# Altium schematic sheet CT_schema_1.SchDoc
size 395 x 454 mm
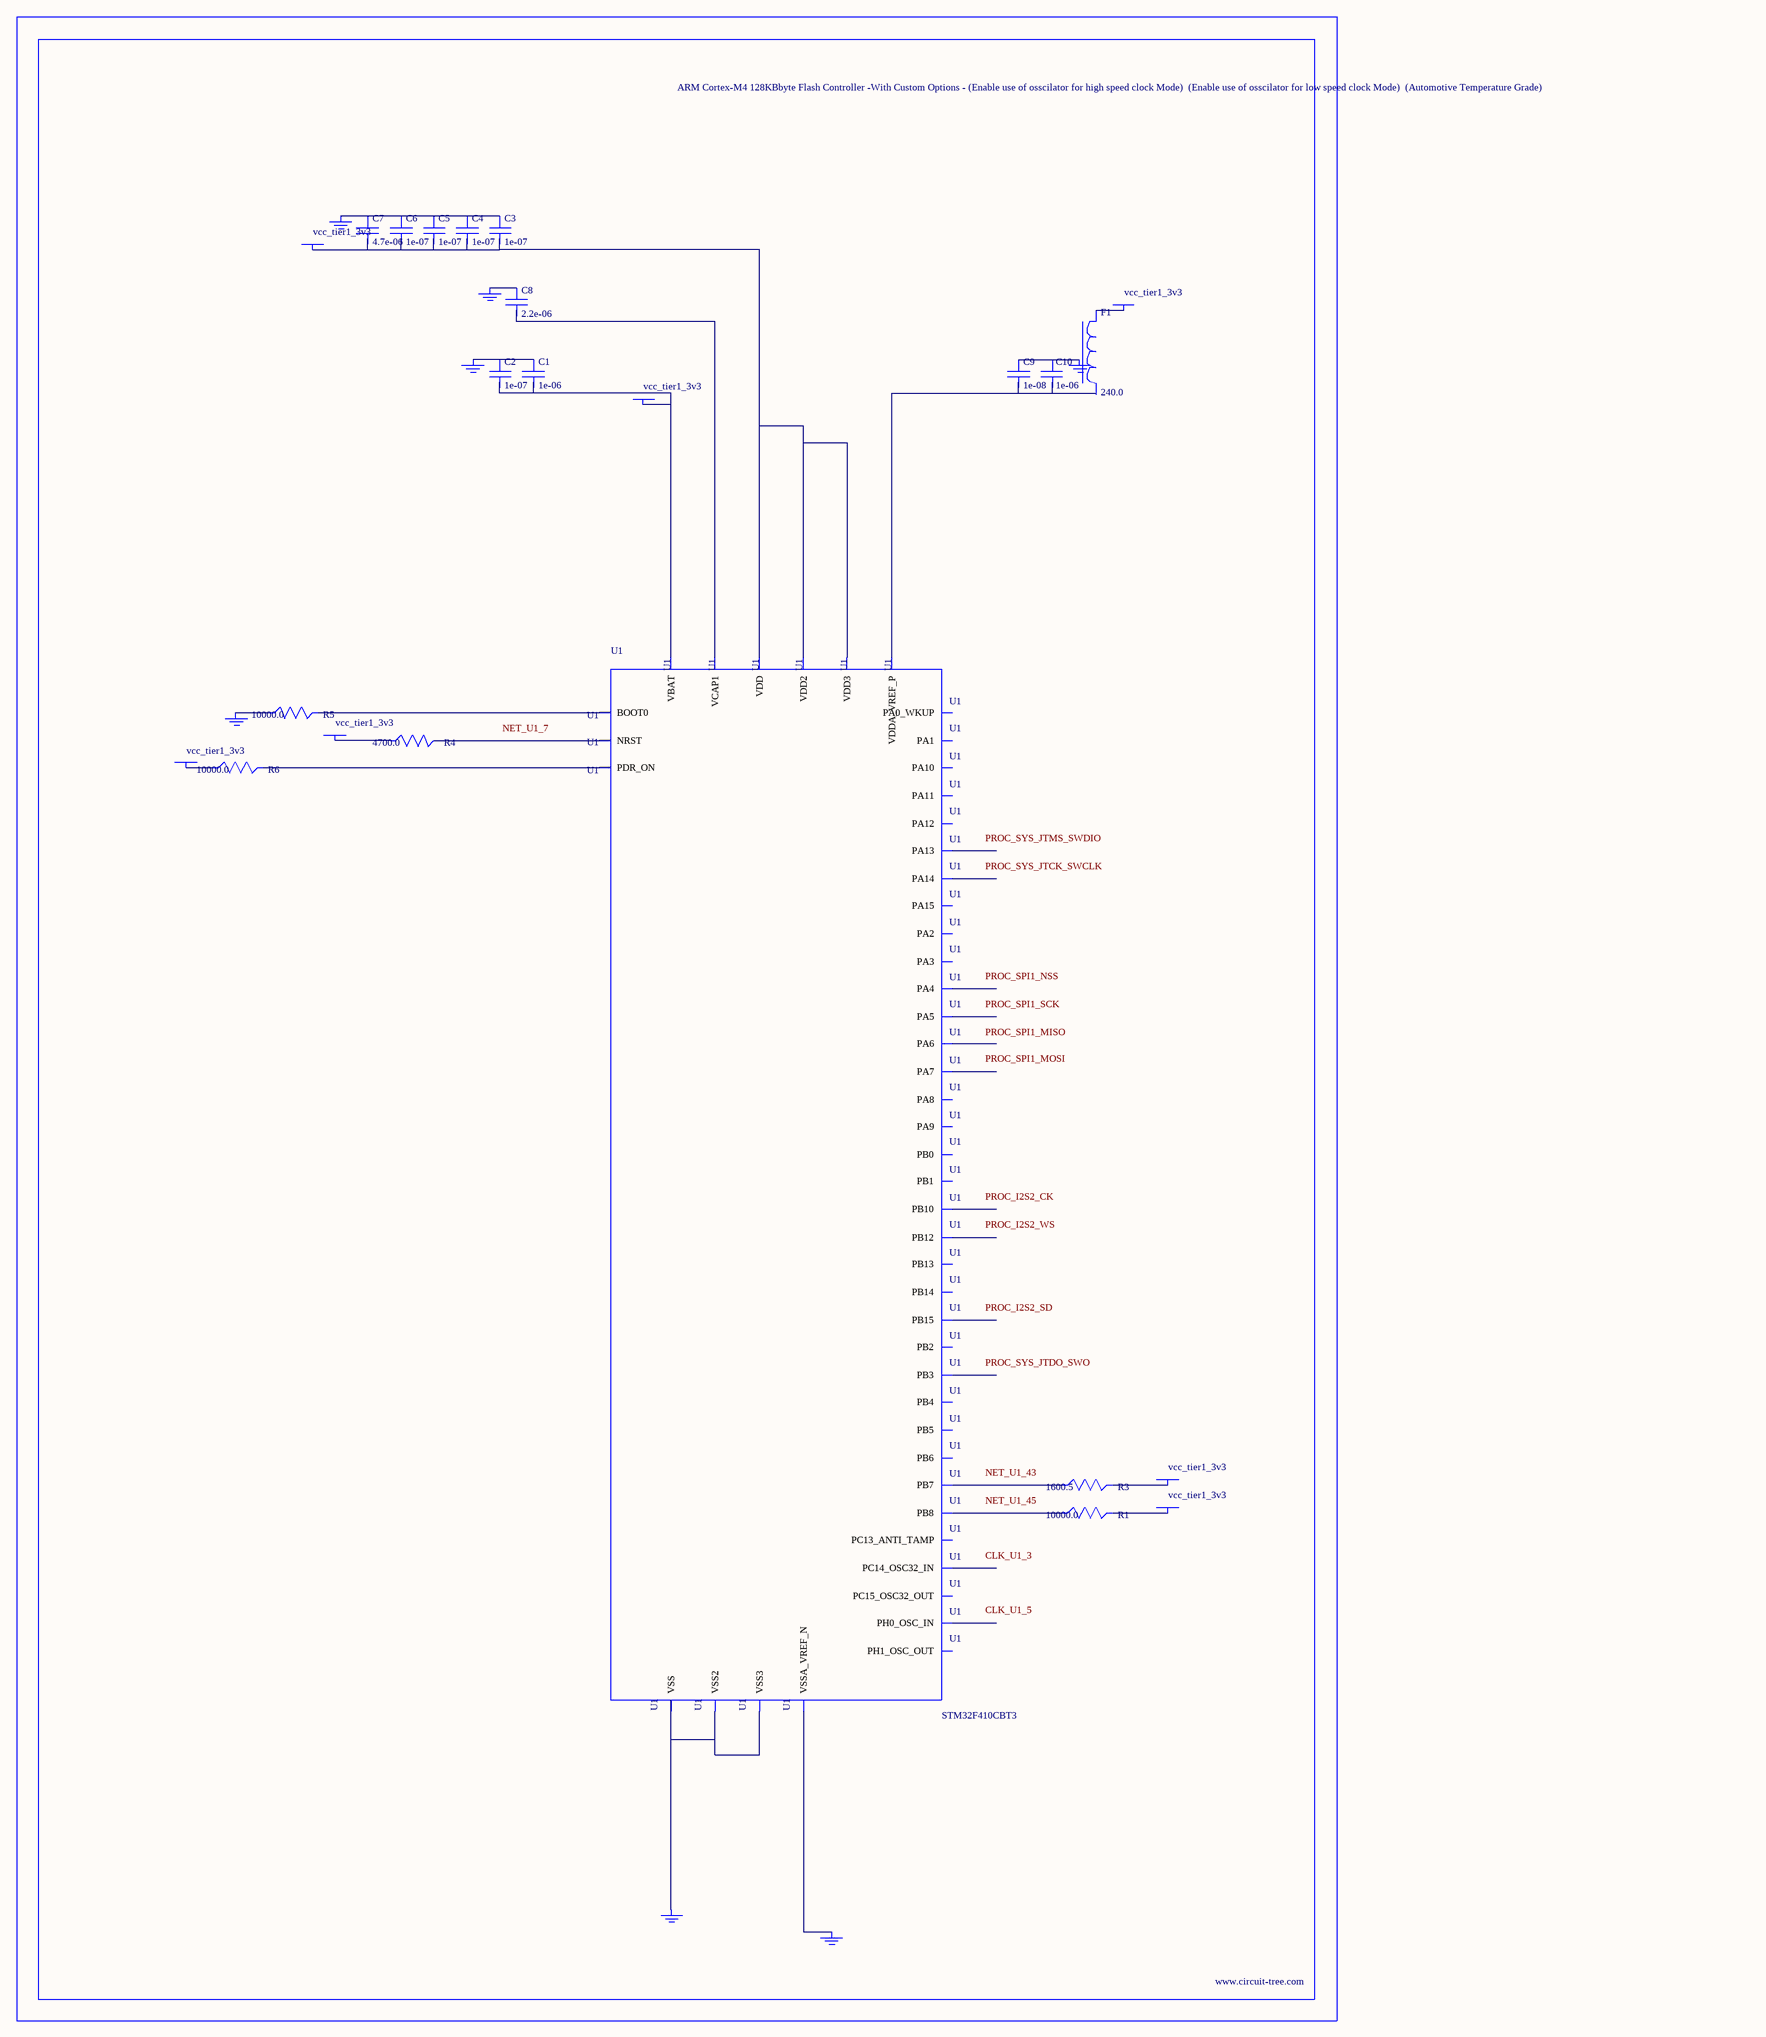
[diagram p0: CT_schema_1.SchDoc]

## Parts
BORDER0  (no value)
C1  1e-06  [C0603]
C2  1e-07  [C0603]
C3  1e-07  [C0603]
C4  1e-07  [C0603]
C5  1e-07  [C0603]
C6  1e-07  [C0603]
C7  4.7e-06  [C0603]
C8  2.2e-06  [C0603]
C9  1e-08  [C0603]
C10  1e-06  [C0603]
F1  240.0  [L0603]
GND_INSTANCE_0_0  (no value)
GND_INSTANCE_0_1  (no value)
GND_INSTANCE_0_2  (no value)
GND_INSTANCE_0_3  (no value)
GND_INSTANCE_0_4  (no value)
GND_INSTANCE_0_5  (no value)
GND_INSTANCE_0_6  (no value)
POWER_INSTANCE_0_0  vcc_tier1_3v3
POWER_INSTANCE_0_1  vcc_tier1_3v3
POWER_INSTANCE_0_2  vcc_tier1_3v3
POWER_INSTANCE_0_3  vcc_tier1_3v3
POWER_INSTANCE_0_4  vcc_tier1_3v3
POWER_INSTANCE_0_5  vcc_tier1_3v3
POWER_INSTANCE_0_6  vcc_tier1_3v3
R1  10000.0  [R0603]
R3  1600.5  [R0603]
R4  4700.0  [R0603]
R5  10000.0  [R0603]
R6  10000.0  [R0603]
U1  STM32F410CBT3  [LQFP48]

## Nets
NetC1_1: C1.1 C2.1 GND_INSTANCE_0_0.0(GND)
NetC1_2: C1.2 C2.2 POWER_INSTANCE_0_0.0(PWR) U1.1(VBAT)
NetC3_1: C3.1 C4.1 C5.1 C6.1 C7.1 GND_INSTANCE_0_4.0(GND)
NetC3_2: C3.2 C4.2 C5.2 C6.2 C7.2 POWER_INSTANCE_0_2.0(PWR) U1.24(VDD) U1.36(VDD2) U1.48(VDD3)
NetC8_1: C8.1 GND_INSTANCE_0_3.0(GND)
NetC8_2: C8.2 U1.22(VCAP1)
NetC9_1: C9.1 C10.1 GND_INSTANCE_0_2.0(GND)
NetC9_2: C9.2 C10.2 U1.9(VDDA_VREF_P)
NetF1_1: F1.1 POWER_INSTANCE_0_1.0(PWR)
NetGND_INSTANCE_0_1_0: GND_INSTANCE_0_1.0(GND) U1.8(VSSA_VREF_N)
NetGND_INSTANCE_0_5_0: GND_INSTANCE_0_5.0(GND) R5.1
NetGND_INSTANCE_0_6_0: GND_INSTANCE_0_6.0(GND) U1.23(VSS) U1.35(VSS2) U1.46(VSS3)
NetPOWER_INSTANCE_0_3_0: POWER_INSTANCE_0_3.0(PWR) R6.1
NetPOWER_INSTANCE_0_4_0: POWER_INSTANCE_0_4.0(PWR) R4.1
NetPOWER_INSTANCE_0_5_0: POWER_INSTANCE_0_5.0(PWR) R3.2
NetPOWER_INSTANCE_0_6_0: POWER_INSTANCE_0_6.0(PWR) R1.2
NetR1_1: R1.1 U1.45(PB8)
NetR3_1: R3.1 U1.43(PB7)
NetR4_2: R4.2 U1.7(NRST)
NetR5_2: R5.2 U1.44(BOOT0)
NetR6_2: R6.2 U1.47(PDR_ON)

Not connected (* = marked no-connect by the designer): F1 2; U1 2(PC13_ANTI_TAMP) 3(PC14_OSC32_IN) 4(PC15_OSC32_OUT) 5(PH0_OSC_IN) 6(PH1_OSC_OUT) 10(PA0_WKUP) 11(PA1) 12(PA2) 13(PA3) 14(PA4) 15(PA5) 16(PA6) 17(PA7) 18(PB0) 19(PB1) 20(PB2) 21(PB10) 25(PB12) 26(PB13) 27(PB14) 28(PB15) 29(PA8) 30(PA9) 31(PA10) 32(PA11) 33(PA12) 34(PA13) 37(PA14) 38(PA15) 39(PB3) 40(PB4) 41(PB5) 42(PB6)

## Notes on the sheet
- Labels drawn without touching a wire or pin: CLK_U1_3, CLK_U1_5, NET_U1_7, NET_U1_43, NET_U1_45, PROC_I2S2_CK, PROC_I2S2_SD, PROC_I2S2_WS, PROC_SPI1_MISO, PROC_SPI1_MOSI, PROC_SPI1_NSS, PROC_SPI1_SCK, PROC_SYS_JTCK_SWCLK, PROC_SYS_JTDO_SWO, PROC_SYS_JTMS_SWDIO

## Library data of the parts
BORDER0 = BORDER_PAGE0
C1 C10 = C0603C105K3RACTU
C2-C6 = 06035C104K4Z2A
C7 = GRM188R6YA475KE15D
C8 = C0603C225K8RACTU
C9 = 06035C103K4Z2A
F1 = Z0603C241ASMST
GND_INSTANCE_0_0-GND_INSTANCE_0_6 = GND
POWER_INSTANCE_0_0-POWER_INSTANCE_0_6 = PWR
R1 R5 R6 = RC0603JR-0710KL
R3 = R3
R4 = RC0603JR-074K7L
